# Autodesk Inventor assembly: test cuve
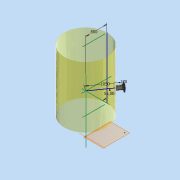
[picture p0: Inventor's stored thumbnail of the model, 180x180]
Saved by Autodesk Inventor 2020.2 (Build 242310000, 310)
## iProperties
Created: 2020-04
Part Number: test cuve
Document SubType Name: Assembly
Designer: t.sancier
_SolveAssemblyDoc: Frame Generator Solve Assembly
_Version: 15.0.0
Author: t.sancier
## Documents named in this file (6)
- F:\inventor\Robustesse maquette numérique\test cuve.iam
- F:\inventor\Robustesse maquette numérique\squelette cuve.ipt
- F:\inventor\Robustesse maquette numérique\virrolr.ipt
- F:\inventor\Robustesse maquette numérique\reforttttt.ipt
- C:\Users\t.sancier\Documents\Inventor\Content Center Files\R2020\fr-FR\DIN EN 1092-2 11 - PN 40\DIN EN 1092-2 Bride à collet soudé 11 - Fonte ductile PN 40 DN150.ipt
- F:\inventor\Robustesse maquette numérique\test cuve\Frame\Frame 1586539677800.iam
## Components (5 placed, 5 different names)
1. squelette cuve:1 — Affleurement:1, Affleurement:2, Affleurement:3, Placage:1, Angle:1
2. virrolr:1 — Affleurement:1, Affleurement:4
3. reforttttt:1 — Affleurement:2
4. DIN EN 1092-2 Bride à collet soudé 11 - Fonte ductile PN 40 DN150:1 — Affleurement:3, Placage:1, Angle:1
5. Frame 1586539677800:1 [sub-assembly] — Affleurement:4
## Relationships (6: Flush 4, Mate 1, Angle 1)
- Affleurement:1 [Flush]: squelette cuve:1 ↔ virrolr:1
- Affleurement:2 [Flush]: squelette cuve:1 ↔ reforttttt:1
- Affleurement:3 [Flush]: squelette cuve:1 ↔ DIN EN 1092-2 Bride à collet soudé 11 - Fonte ductile PN 40 DN150:1
- Placage:1 [Mate]: squelette cuve:1 ↔ DIN EN 1092-2 Bride à collet soudé 11 - Fonte ductile PN 40 DN150:1
- Angle:1: squelette cuve:1 ↔ DIN EN 1092-2 Bride à collet soudé 11 - Fonte ductile PN 40 DN150:1
- Affleurement:4 [Flush]: virrolr:1 ↔ Frame 1586539677800:1
